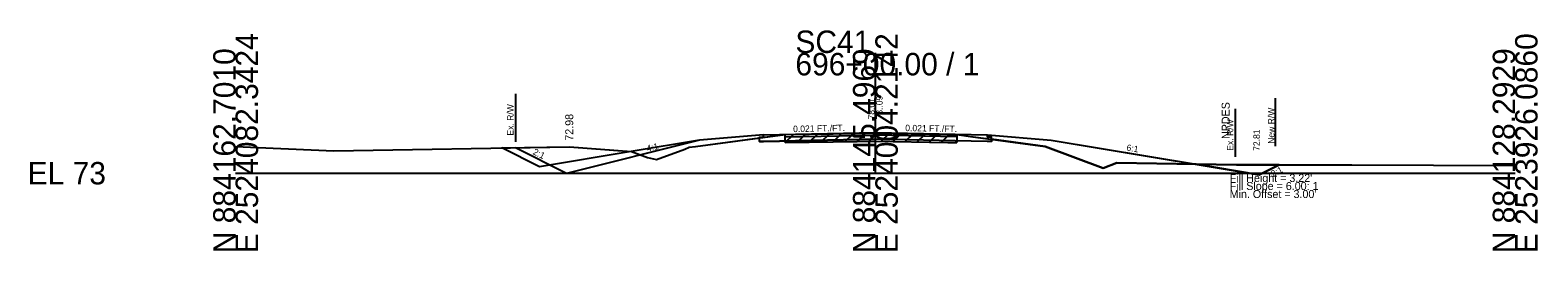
# Model space of a CAD drawing. Extents: x -26 to 183, y -10 to 24021.
# Drawn here: x -25.7 to 162.8, y 19990.3 to 20017.9 of the extents above; entities that cross this region are included whole.
import ezdxf

# ---------------------------------------------------------------- set-up
doc = ezdxf.new("R2010")
doc.units = 0
for name, color, linetype in [('RD_GPK_XS_Cell', 7, 'Continuous'), ('RD_XS_Base', 7, 'Continuous'), ('RD_XS_Buildup', 7, 'Continuous'), ('RD_XS_EarthShd', 7, 'Continuous'), ('RD_XS_EwShp', 7, 'Continuous'), ('RD_XS_ExGround', 7, 'Continuous'), ('RD_XS_ExPaveRet', 7, 'Continuous'), ('RD_XS_ExRW', 7, 'Continuous'), ('RD_XS_NewRW', 7, 'Continuous'), ('RD_XS_Pave', 7, 'Continuous'), ('RD_XS_TieSlope', 7, 'Continuous'), ('RD_XS_TX_Elev_EX', 7, 'Continuous'), ('RD_XS_TX_Elev_PR', 7, 'Continuous'), ('RD_XS_TX_Slope', 7, 'Continuous'), ('RD_XS_TX_Warning', 7, 'Continuous')]:
    doc.layers.add(name, color=color, linetype=linetype)

msp = doc.modelspace()

# ---------------------------------------------------------------- linework, layer by layer
at = {"layer": 'RD_GPK_XS_Cell'}
for p, q in [((80, 20000), (80, 20015.02)), ((0, 20000), (80, 20000)), ((80, 20000), (160, 20000))]:
    msp.add_line(p, q, dxfattribs=at)
at = {"layer": 'RD_XS_Base'}
for p in [(66.01, 20003.96), (93.99, 20003.96)]:
    msp.add_line(p, (80, 20004.25), dxfattribs=at)
at = {"layer": 'RD_XS_Buildup'}
for p, q in [((68.73, 20004.54), (80, 20004.77)), ((68.73, 20004.64), (68.73, 20004.65)), ((90.2, 20004.56), (80, 20004.77))]:
    msp.add_line(p, q, dxfattribs=at)
at = {"layer": 'RD_XS_EarthShd'}
for p, q in [((66, 20004.8), (58, 20004.13)), ((94, 20004.8), (102, 20004.13))]:
    msp.add_line(p, q, dxfattribs=at)
at = {"layer": 'RD_XS_EwShp'}
for points in [[(56.16, 20003.01), (56.73, 20003.27), (57.52, 20003.35), (65.5, 20004.4), (65.5, 20004.5), (66, 20004.51), (66, 20004.8), (58, 20004.13), (49.48, 20002.71), (49.51, 20002.71), (51.51, 20001.95), (52.64, 20001.72)], [(51.51, 20001.95), (52.64, 20001.72), (56.16, 20003.01), (56.73, 20003.27), (57.52, 20003.35), (65.5, 20004.4), (65.5, 20004.5), (66, 20004.51), (66, 20004.8), (58, 20004.13), (49.48, 20002.71), (49.51, 20002.71)], [(51.51, 20001.95), (52.64, 20001.72), (56.16, 20003.01), (56.73, 20003.27), (57.52, 20003.35), (65.5, 20004.4), (65.5, 20004.5), (66, 20004.51), (66, 20004.8), (58, 20004.13), (49.48, 20002.71), (49.51, 20002.71)], [(68.73, 20004.82), (77.71, 20004.97), (79.92, 20005.01), (89.06, 20004.84), (90.2, 20004.82), (91.88, 20004.59), (94.5, 20004.24), (94.5, 20003.95), (93.99, 20003.96), (80, 20004.25), (66.01, 20003.96), (65.5, 20003.95), (65.5, 20004.4)], [(90.2, 20004.82), (91.88, 20004.59), (94.5, 20004.24), (94.5, 20003.95), (93.99, 20003.96), (80, 20004.25), (66.01, 20003.96), (65.5, 20003.95), (65.5, 20004.4), (68.73, 20004.82), (77.71, 20004.97), (79.92, 20005.01), (89.06, 20004.84)], [(90.2, 20004.82), (91.88, 20004.59), (94.5, 20004.24), (94.5, 20003.95), (93.99, 20003.96), (80, 20004.25), (66.01, 20003.96), (65.5, 20003.95), (65.5, 20004.4), (68.73, 20004.82), (77.71, 20004.97), (79.92, 20005.01), (89.06, 20004.84)], [(94.5, 20004.24), (94.5, 20004.5), (94, 20004.51), (94, 20004.8), (102, 20004.13), (120.1, 20001.12), (110.21, 20001.29), (108.48, 20000.63), (101.23, 20003.33)], [(94.5, 20004.24), (94.5, 20004.5), (94, 20004.51), (94, 20004.8), (102, 20004.13), (120.1, 20001.12), (110.21, 20001.29), (108.48, 20000.63), (101.23, 20003.33)], [(94.5, 20004.24), (94.5, 20004.5), (94, 20004.51), (94, 20004.8), (102, 20004.13), (120.1, 20001.12), (110.21, 20001.29), (108.48, 20000.63), (101.23, 20003.33)], [(33.3, 20003.15), (41.75, 20003.29), (49.48, 20002.71), (38, 20000.8)], [(38, 20000.8), (33.3, 20003.15), (41.75, 20003.29), (49.48, 20002.71)], [(38, 20000.8), (33.3, 20003.15), (41.75, 20003.29), (49.48, 20002.71)], [(125.14, 20001.03), (130.48, 20001.03), (128.01, 19999.8), (120.1, 20001.12)], [(128.01, 19999.8), (130.48, 20001.03), (125.14, 20001.03), (120.1, 20001.12)], [(128.01, 19999.8), (130.48, 20001.03), (125.14, 20001.03), (120.1, 20001.12)]]:
    msp.add_lwpolyline(points, close=True, dxfattribs=at)
at = {"layer": 'RD_XS_ExGround'}
for p, q in [((0, 20003.33), (12.3, 20002.78)), ((56.73, 20003.27), (57.52, 20003.35)), ((57.52, 20003.35), (68.73, 20004.82)), ((68.73, 20004.82), (77.71, 20004.97)), ((77.71, 20004.97), (79.92, 20005.01)), ((79.92, 20005.01), (89.06, 20004.84)), ((89.06, 20004.84), (90.2, 20004.82)), ((90.2, 20004.82), (91.88, 20004.59)), ((91.88, 20004.59), (101.23, 20003.33)), ((101.23, 20003.33), (108.48, 20000.63)), ((12.3, 20002.78), (41.75, 20003.29)), ((41.75, 20003.29), (49.51, 20002.71)), ((49.51, 20002.71), (51.51, 20001.95)), ((51.51, 20001.95), (52.64, 20001.72)), ((52.64, 20001.72), (56.16, 20003.01)), ((56.16, 20003.01), (56.73, 20003.27)), ((108.48, 20000.63), (110.21, 20001.29)), ((110.21, 20001.29), (125.14, 20001.03)), ((125.14, 20001.03), (139.57, 20001.03)), ((139.57, 20001.03), (160, 20000.97))]:
    msp.add_line(p, q, dxfattribs=at)
at = {"layer": 'RD_XS_ExPaveRet'}
for p, q in [((68.73, 20003.82), (69.75, 20004.84)), ((68.73, 20003.82), (68.73, 20004.82)), ((68.73, 20003.82), (77.71, 20003.97)), ((70.23, 20003.85), (71.25, 20004.87)), ((71.73, 20003.87), (72.75, 20004.89)), ((73.23, 20003.9), (74.25, 20004.92)), ((74.73, 20003.92), (75.75, 20004.94)), ((76.23, 20003.95), (77.25, 20004.97)), ((77.71, 20003.97), (79.92, 20004.01)), ((77.73, 20003.97), (78.75, 20004.99)), ((79.23, 20004), (80.24, 20005)), ((79.92, 20004.01), (89.06, 20003.84)), ((80.73, 20003.99), (81.72, 20004.97)), ((82.23, 20003.96), (83.22, 20004.95)), ((83.73, 20003.94), (84.72, 20004.92)), ((85.23, 20003.91), (86.22, 20004.89)), ((86.73, 20003.88), (87.72, 20004.86)), ((88.23, 20003.85), (89.22, 20004.84)), ((89.06, 20003.84), (90.2, 20003.82)), ((90.2, 20004.82), (90.2, 20003.82))]:
    msp.add_line(p, q, dxfattribs=at)
at = {"layer": 'RD_XS_ExRW'}
for p, q in [((35, 20009.91), (35, 20003.91)), ((125, 20008.03), (125, 20002.03))]:
    msp.add_line(p, q, dxfattribs=at)
at = {"layer": 'RD_XS_NewRW'}
msp.add_line((130, 20009.37), (130, 20003.37), dxfattribs=at)
at = {"layer": 'RD_XS_Pave'}
for p, q in [((65.5, 20004.5), (66, 20004.51)), ((65.5, 20003.95), (65.5, 20004.5)), ((65.5, 20003.95), (66.01, 20003.96)), ((66, 20004.8), (80, 20005.09)), ((66, 20004.51), (66, 20004.8)), ((80, 20005.09), (93.99, 20004.8)), ((94.5, 20003.95), (93.99, 20003.96)), ((94, 20004.51), (94, 20004.8)), ((94.5, 20004.5), (94, 20004.51)), ((94.5, 20003.95), (94.5, 20004.5))]:
    msp.add_line(p, q, dxfattribs=at)
at = {"layer": 'RD_XS_TieSlope'}
for p, q in [((58, 20004.13), (41.39, 19999.98)), ((102, 20004.13), (128.01, 19999.8)), ((41.39, 19999.98), (35, 20003.18)), ((128.01, 19999.8), (130.48, 20001.03))]:
    msp.add_line(p, q, dxfattribs=at)

# ---------------------------------------------------------------- texts
at = {"layer": 'RD_GPK_XS_Cell'}
for s, p in [('E 2524082.3424', (2.8, 19990)), ('E 2524004.2142', (82.8, 19990)), ('E 2523926.0860', (162.8, 19990)), ('N 884162.7010', (0, 19990)), ('N 884145.4969', (80, 19990)), ('N 884128.2929', (160, 19990))]:
    msp.add_text(s, height=2.8, rotation=90, dxfattribs=at).set_placement(p)
for s, p in [('SC41', (70, 20015.02)), ('696+00.00 / 1', (70, 20012.22)), ('EL 73', (-26, 19998.6))]:
    msp.add_text(s, height=2.8, dxfattribs=at).set_placement(p)
at = {"layer": 'RD_XS_ExRW'}
for p in [(34.75, 20004.7), (124.75, 20002.81)]:
    msp.add_text('Ex. R/W ', height=0.8, rotation=90, dxfattribs=at).set_placement(p)
at = {"layer": 'RD_XS_NewRW'}
msp.add_text('New R/W ', height=0.8, rotation=90, dxfattribs=at).set_placement((129.9, 20003.67))
at = {"layer": 'RD_XS_TX_Elev_EX'}
msp.add_text('78.01', height=0.8, rotation=90, dxfattribs=at).set_placement((79.9, 20006.71))
at = {"layer": 'RD_XS_TX_Elev_PR'}
for s, height, p in [('78..09', 0.8, (80.9, 20006.71)), ('72.98', 1, (42.22, 20004.06)), ('72.81', 0.8, (128.07, 20002.79))]:
    msp.add_text(s, height=height, rotation=90, dxfattribs=at).set_placement(p)
at = {"layer": 'RD_XS_TX_Slope'}
for s, rotation, p in [('0.021 FT./FT.', 1.1916, (69.72, 20005.13)), ('0.021 FT./FT.', 358.8084, (83.73, 20005.26)), ('4:1', 14.0362, (51.5, 20002.67)), ('6:1', 350.5377, (111.36, 20002.83)), ('2:1', 333.4349, (37.1, 20002.41)), ('2:1', 26.5651, (129.7, 19999.5))]:
    msp.add_text(s, height=0.8, rotation=rotation, dxfattribs=at).set_placement(p)
at = {"layer": 'RD_XS_TX_Warning'}
msp.add_text(' NPDES', height=1, rotation=90, dxfattribs=at).set_placement((124.3, 20003.9))
for s, p in [("Fill Height = 3.22' ", (124.3, 19998.9)), ('Fill Slope = 6.00: 1', (124.3, 19997.9)), ("Min. Offset = 3.00' ", (124.3, 19996.9))]:
    msp.add_text(s, height=1, dxfattribs=at).set_placement(p)

doc.saveas('drawing.dxf')
